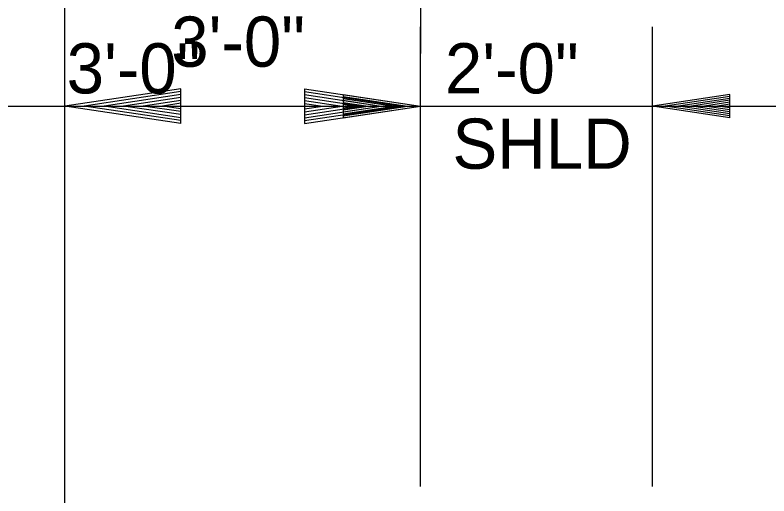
# Model space of a CAD drawing. Extents: x 1373719 to 1374161, y 379835 to 380167.
# Drawn here: x 1373940.61 to 1373950.36, y 379977.95 to 379984.17 of the extents above; entities that cross this region are included whole.
import ezdxf

# ---------------------------------------------------------------- set-up
doc = ezdxf.new("R2010")
doc.units = 0
doc.layers.add('GREEN_TXT', color=7, linetype='Continuous')
doc.layers.add('Text 1', color=7, linetype='Continuous')

msp = doc.modelspace()

# ---------------------------------------------------------------- linework, layer by layer
at = {"layer": 'GREEN_TXT'}
for p, q in [((1373945.8548, 379986.2001), (1373945.8548, 379983.6738)), ((1373945.8548, 379978.0678), (1373945.8548, 379984.0193)), ((1373948.8548, 379978.0678), (1373948.8548, 379984.0193)), ((1373944.8548, 379983.1418), (1373945.8548, 379982.9918)), ((1373944.8548, 379983.1418), (1373944.8548, 379982.8418)), ((1373949.8548, 379983.1418), (1373948.8548, 379982.9918)), ((1373949.8548, 379982.8418), (1373949.8548, 379983.1418)), ((1373944.8548, 379983.1168), (1373945.6878, 379982.9918)), ((1373944.8548, 379983.0913), (1373945.5158, 379982.9918)), ((1373944.8548, 379983.0663), (1373945.3493, 379982.9918)), ((1373944.8548, 379983.0403), (1373945.1798, 379982.9918)), ((1373949.8548, 379983.1168), (1373949.0218, 379982.9918)), ((1373949.8548, 379983.0913), (1373949.1938, 379982.9918)), ((1373949.8548, 379983.0663), (1373949.3603, 379982.9918)), ((1373949.8548, 379983.0408), (1373949.5298, 379982.9918)), ((1373938.7049, 379982.9918), (1373945.8548, 379982.9918)), ((1373944.8548, 379983.0153), (1373945.0128, 379982.9918)), ((1373944.8548, 379982.8418), (1373945.8548, 379982.9918)), ((1373944.8548, 379982.9428), (1373945.1798, 379982.9918)), ((1373944.8548, 379982.8923), (1373945.5158, 379982.9918)), ((1373944.8548, 379982.8668), (1373945.6878, 379982.9918)), ((1373944.8548, 379982.9173), (1373945.3493, 379982.9918)), ((1373944.8548, 379982.9683), (1373945.0128, 379982.9918)), ((1373945.8548, 379982.9918), (1373948.8548, 379982.9918)), ((1373948.8548, 379982.9918), (1373965.3548, 379982.9918)), ((1373949.8548, 379982.8418), (1373948.8548, 379982.9918)), ((1373949.8548, 379982.8668), (1373949.0218, 379982.9918)), ((1373949.8548, 379982.8923), (1373949.1938, 379982.9918)), ((1373949.8548, 379982.9173), (1373949.3603, 379982.9918)), ((1373949.8548, 379982.9433), (1373949.5298, 379982.9918)), ((1373949.8548, 379983.0153), (1373949.6968, 379982.9918)), ((1373949.8548, 379982.9683), (1373949.6968, 379982.9918))]:
    msp.add_line(p, q, dxfattribs=at)
at = {"layer": 'Text 1'}
for p, q in [((1373941.2581, 379977.1383), (1373941.2581, 379999.1359)), ((1373942.7581, 379983.2168), (1373941.2581, 379982.9918)), ((1373942.7581, 379982.7668), (1373942.7581, 379983.2168)), ((1373944.3548, 379983.2168), (1373945.8548, 379982.9918)), ((1373944.3548, 379983.2168), (1373944.3548, 379982.7668)), ((1373942.7581, 379983.1793), (1373941.5086, 379982.9918)), ((1373942.7581, 379983.1418), (1373941.7666, 379982.9918)), ((1373944.3548, 379983.1793), (1373945.6043, 379982.9918)), ((1373944.3548, 379983.1403), (1373945.3463, 379982.9918)), ((1373942.7581, 379983.1028), (1373942.0171, 379982.9918)), ((1373942.7581, 379983.0653), (1373942.2706, 379982.9918)), ((1373942.7581, 379983.0278), (1373942.5211, 379982.9918)), ((1373944.3548, 379983.1028), (1373945.0973, 379982.9918)), ((1373944.3548, 379983.0638), (1373944.8423, 379982.9918)), ((1373944.3548, 379983.0263), (1373944.5918, 379982.9918)), ((1373942.7581, 379982.7668), (1373941.2581, 379982.9918)), ((1373941.2581, 379982.9918), (1373945.8548, 379982.9918)), ((1373942.7581, 379982.8043), (1373941.5086, 379982.9918)), ((1373942.7581, 379982.8418), (1373941.7666, 379982.9918)), ((1373942.7581, 379982.8808), (1373942.0171, 379982.9918)), ((1373942.7581, 379982.9198), (1373942.2706, 379982.9918)), ((1373942.7581, 379982.9558), (1373942.5211, 379982.9918)), ((1373944.3548, 379982.7668), (1373945.8548, 379982.9918)), ((1373944.3548, 379982.9183), (1373944.8423, 379982.9918)), ((1373944.3548, 379982.8418), (1373945.3463, 379982.9918)), ((1373944.3548, 379982.8043), (1373945.6043, 379982.9918)), ((1373944.3548, 379982.8793), (1373945.0973, 379982.9918)), ((1373944.3548, 379982.9558), (1373944.5918, 379982.9918))]:
    msp.add_line(p, q, dxfattribs=at)

# ---------------------------------------------------------------- texts
at = {"layer": 'GREEN_TXT'}
for s, p in [('3\'-0"', (1373941.281, 379983.1553)), ('2\'-0"', (1373946.1719, 379983.1553)), ('SHLD', (1373946.2691, 379982.1803))]:
    msp.add_text(s, height=0.65, dxfattribs=at).set_placement(p)
at = {"layer": 'Text 1'}
msp.add_text('3\'-0"', height=0.65, dxfattribs=at).set_placement((1373942.6332, 379983.5014))

doc.saveas('drawing.dxf')
